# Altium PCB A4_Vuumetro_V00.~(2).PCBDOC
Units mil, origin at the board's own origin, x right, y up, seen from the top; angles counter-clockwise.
Board outline 6000 x 4000 mil, 2 copper layers (Top Layer, Bottom Layer); 34 components, 37 nets, 68 pads, 0 vias.
Unrouted connection lines stored in the file: 33.
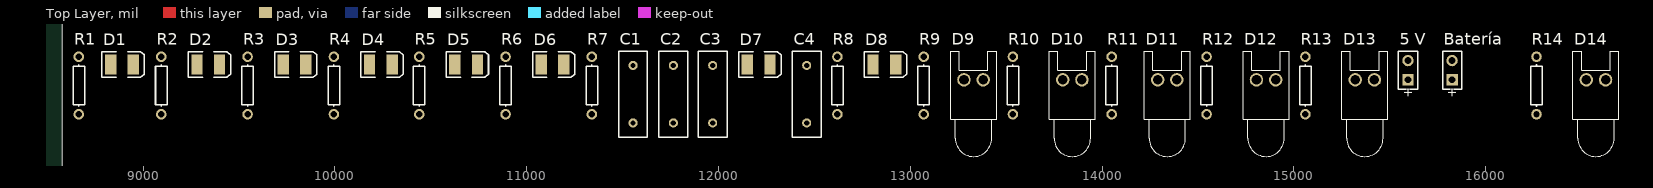
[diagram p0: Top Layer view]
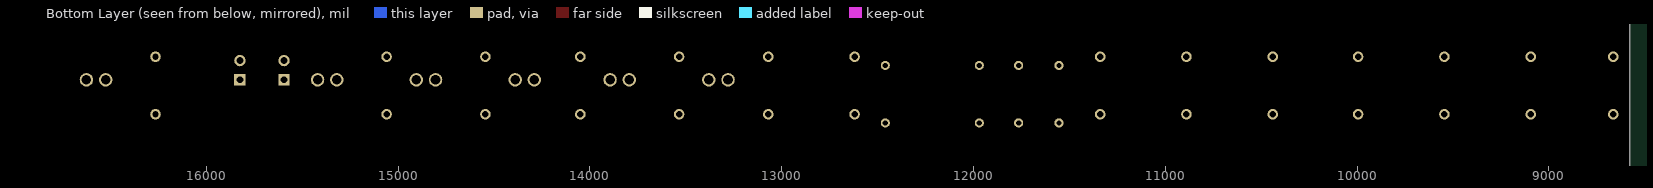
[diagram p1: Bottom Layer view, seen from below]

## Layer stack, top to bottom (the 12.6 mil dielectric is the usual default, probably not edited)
Top Solder: solder mask 0.4, Solder Resist, Dk 3.5
Top Layer: signal copper 1.4
Dielectric1: dielectric 12.6, FR-4, Dk 4.8
Bottom Layer: signal copper 1.4
Bottom Solder: solder mask 0.4, Solder Resist, Dk 3.5

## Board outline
2580,2130 2580,6130 8580,6130 8580,2130

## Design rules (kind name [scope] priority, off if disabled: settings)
Clearance [All] p1: gap=10
FabricationTestPointUsage TestPointUsage [All] p1: valid=0 allowmultiple=FALSE
FabricationTestpoint Testpoint [All] p1: side=3 testpointundercomponent=TRUE minsize=40 maxsize=100 preferedsize=60 minholesize=0 maxholesize=40 preferedholesize=32 testpointgrid=1 allowsidetop=TRUE allowsidebottom=TRUE usegrid=TRUE gridtolerance=0.01
PolygonConnect [All] p1: connectstyle=Relief reliefconductorwidth=10 reliefentries=4 polygonreliefangle="90 Angle" airgapwidth=10
RoomDefinition ProyectoIntegrado_V00 [InComponentClass('ProyectoIntegrado_V00')] p1: confinementstyle=ConfineIn formatcopy=TRUE lockcomponents=FALSE outline 8625,2190 16705,2190 16705,2860 8625,2860
RoutingVias [All] p1: holewidth=28 width=50 viastyle="Through Hole" minholewidth=28 minwidth=50 maxholewidth=28 maxwidth=50
SilkToSolderMaskClearance SilkscreenOverComponentPads [IsPad] p1: minsilkscreentomaskgap=10 clearancetoexposedcopper=TRUE
SolderMaskExpansion [All] p1: expansion=4
Width [All] p1: maxlimit=10 minlimit=10 preferedwidth=10
27 further rules are at their usual default settings.

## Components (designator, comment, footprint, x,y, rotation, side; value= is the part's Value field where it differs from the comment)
"5 V" "Batería" BAT-2 15595,2650 r90 top
Batería "3.2 V" BAT-2 15825,2650 r90 top
C1 "Cap" RAD-0.3 11555,2525 r90 top
C2 "Cap" RAD-0.3 11765,2525 r90 top
C3 "Cap" RAD-0.3 11970,2525 r90 top
C4 "Cap" RAD-0.3 12460,2525 r90 top
D1 "LED3" 3.5X2.8X1.9 8890,2680 r0 top
D2 "LED3" 3.5X2.8X1.9 9340,2680 r0 top
D3 "LED3" 3.5X2.8X1.9 9790,2680 r0 top
D4 "LED3" 3.5X2.8X1.9 10240,2680 r0 top
D5 "LED3" 3.5X2.8X1.9 10685,2680 r0 top
D6 "LED3" 3.5X2.8X1.9 11135,2680 r0 top
D7 "LED3" 3.5X2.8X1.9 12210,2680 r0 top
D8 "LED3" 3.5X2.8X1.9 12865,2680 r0 top
D9 "ED0" LED-0 13330,2600 r0 top
D10 "LED0" LED-0 13845,2600 r0 top
D11 "LED0" LED-0 14340,2600 r0 top
D12 "LED0" LED-0 14855,2600 r0 top
D13 "LED0" LED-0 15370,2600 r0 top
D14 "LED0" LED-0 16575,2600 r0 top
R1 "Res1" AXIAL-0.3 8665,2570 r90 top
R2 "Res1" AXIAL-0.3 9095,2570 r90 top
R3 "Res1" AXIAL-0.3 9545,2570 r90 top
R4 "Res1" AXIAL-0.3 9995,2570 r90 top
R5 "Res1" AXIAL-0.3 10440,2570 r90 top
R6 "Res1" AXIAL-0.3 10890,2570 r90 top
R7 "Res1" AXIAL-0.3 11340,2570 r90 top
R8 "Res1" AXIAL-0.3 12620,2570 r90 top
R9 "Res1" AXIAL-0.3 13070,2570 r90 top
R10 "Res1" AXIAL-0.3 13535,2570 r90 top
R11 "Res1" AXIAL-0.3 14050,2570 r90 top
R12 "Res1" AXIAL-0.3 14545,2570 r90 top
R13 "Res1" AXIAL-0.3 15060,2570 r90 top
R14 "Res1" AXIAL-0.3 16265,2570 r90 top

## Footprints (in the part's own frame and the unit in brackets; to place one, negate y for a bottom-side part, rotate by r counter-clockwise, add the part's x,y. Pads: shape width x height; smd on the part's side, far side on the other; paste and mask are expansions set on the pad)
3.5X2.8X1.9 [mm] "SM LED; 2 C-Bend Leads; Body 3.5 x 2.8 x 1.9 mm, inc leads (LxWxH typ)"
  rect 1.5x2.6 smd: 1(-1.5,0) 2(1.5,0)
  silkscreen extent -2.65,-1.7 2.95,1.7
AXIAL-0.3 [mm] "Axial Device, Thru-Hole; 2 Leads; 0.3 in Pin Spacing"
  round 1.4 hole 0.85: 1(-3.81,0) 2(3.81,0)
  silkscreen extent -2.77,-0.76 2.77,0.76
BAT-2 [mm] "Battery; 2 Leads"
  rect 1.5x1.5 hole 0.9: 1(-1.27,0)
  round 1.5 hole 0.9: 2(1.27,0)
  silkscreen extent -2.54,-1.27 2.54,1.27
LED-0 [mil] "LED; 2 Leads"
  round 70 hole 50: 1(50,0) 2(-50,0)
  silkscreen extent -120,-400 120,150
RAD-0.3 [mm] "Radial Cap, Thru-Hole; 2 Leads; 0.3 in Pin Spacing"
  round 1.2 hole 0.7: 1(-3.81,0) 2(3.81,0)
  silkscreen extent -5.71,-1.91 5.71,1.91

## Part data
"5 V" Batería: library part Battery, "Multicell Battery"
C1 C2 C3 C4: "Capacitor"
D1 D2 D3 D4 D5 D6 D7 D8: "Typical BLUE SiC LED"
D9: library part LED0, "Typical INFRARED GaAs LED"
D10 D11 D12 D13 D14: "Typical INFRARED GaAs LED"
R1 R2 R3 R4 R5 R6 R7 R8 R9 R10 R11 R12 R13 R14: "Resistor"

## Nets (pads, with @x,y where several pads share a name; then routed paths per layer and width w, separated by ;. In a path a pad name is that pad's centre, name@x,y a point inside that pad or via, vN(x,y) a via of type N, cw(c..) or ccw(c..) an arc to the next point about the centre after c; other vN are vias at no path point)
"5 V": C1.2 C2.2 C3.2 R1.2 R2.2 R3.2 R4.2 R5.2 R6.2 R7.2 R8.2 R9.2 R10.2 R11.2 R12.2 R13.2 R14.2
"ANALOGIC 0": 
"DIGITAL 0": D1.2
"DIGITAL 1": D2.2
"DIGITAL 2": D3.2
"DIGITAL 3": D4.2
"DIGITAL 4": D5.2
"DIGITAL 5": D6.2
"DIGITAL 6": D7.2
"DIGITAL 7": D8.2
"DIGITAL 8": D9.2
"DIGITAL 9": D10.2
"DIGITAL 10": D11.2
"DIGITAL 11": D12.2
"DIGITAL 12": D13.2
"DIGITAL 13": D14.2
GND: C1.1 C2.1 C3.1 C4.1
"Net5 V_1": "5 V.1"
"Net5 V_2": "5 V.2"
NetBatería_1: Batería.1
NetBatería_2: Batería.2
NetC4_2: C4.2
NetD1_1: D1.1 R1.1
NetD2_1: D2.1 R2.1
NetD3_1: D3.1 R3.1
NetD4_1: D4.1 R4.1
NetD5_1: D5.1 R5.1
NetD6_1: D6.1 R6.1
NetD7_1: D7.1 R7.1
NetD8_1: D8.1 R8.1
NetD9_1: D9.1 R9.1
NetD10_1: D10.1 R10.1
NetD11_1: D11.1 R11.1
NetD12_1: D12.1 R12.1
NetD13_1: D13.1 R13.1
NetD14_1: D14.1 R14.1
NetU1_42: 

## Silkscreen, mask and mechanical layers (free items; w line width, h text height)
Mechanical 16:
  drawing of 1874 lines, arcs and shapes, not listed
  text "1" at 1427,7465 h70
  text "2" at 4287,7465 h70
  text "3" at 7167,7465 h70
  text "4" at 10037,7465 h70
  text "A" at 75,6559 h70
  text "A" at 11375,6559 h70
  text "B" at 75,4667 h70
  text "B" at 11375,4667 h70
  text "C" at 75,2757 h70
  text "C" at 11375,2757 h70
  text "ENGINEER:" at 6850,1300 h45
  text "TITLE:" at 8350,1300 h45
  text "PCB DESIGNER:" at 6850,1005 h45
  text "D" at 75,867 h70
  text "D" at 11375,867 h70
  text "DATE:" at 6850,700 h45
  text "PART NO.:" at 8350,700 h45
  text "REV:" at 10450,700 h45
  text "Altium Limited" at 5550,600 h70
  text ".PRINT_DATE" at 6900,580 h70
  text "12a Rodborough Rd" at 5550,500 h70
  text "Frenchs Forest" at 5550,400 h70
  text "FILE NAME:" at 6850,400 h45
  text "DWG NO:" at 8350,400 h45
  text "SCALE:" at 10450,400 h45
  text "NSW 2086" at 5550,300 h70
  text ".PCB_FILE_NAME_NO_PATH" at 6900,280 h70
  text "1" at 1427,65 h70
  text "2" at 4287,65 h70
  text "3" at 7167,65 h70
  text "4" at 10037,65 h70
